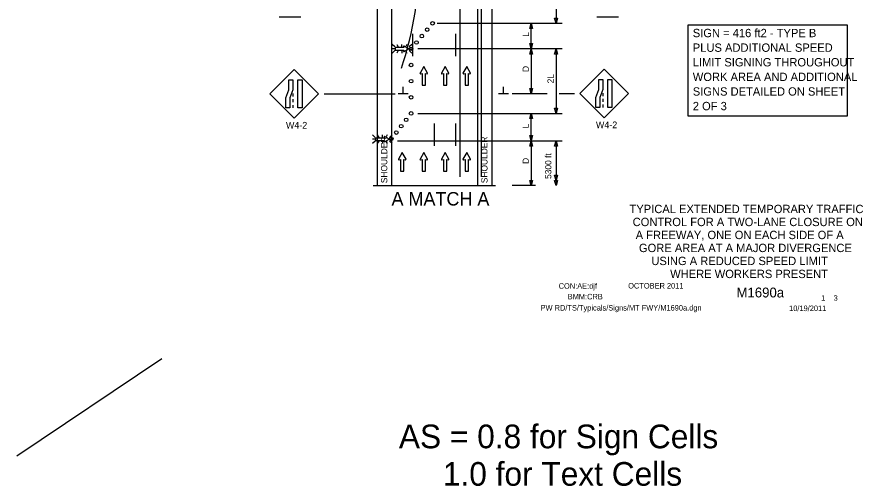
# Model space of a CAD drawing. Extents: x 16486 to 19506, y 5576 to 7023.
# Drawn here: x 16486 to 17431, y 5738 to 6261 of the extents above; entities that cross this region are included whole.
import ezdxf

# ---------------------------------------------------------------- set-up
doc = ezdxf.new("R2010")
doc.units = 0
for name, color, linetype in [('ALI_LEGAL_EX', 7, 'Continuous'), ('BORDER', 7, 'Continuous'), ('BORDER_SIGNAL_WO', 7, 'Continuous'), ('MT_SCRATCH_LEVEL_E', 7, 'Continuous'), ('PAVT_EDGE_EX', 7, 'Continuous'), ('TRAFFIC_SIGNS_PR', 7, 'Continuous'), ('TYPICAL_TEXT_DIMEN_EX', 7, 'Continuous'), ('TYPICAL_TEXT_DIMEN_PR', 7, 'Continuous')]:
    doc.layers.add(name, color=color, linetype=linetype)

msp = doc.modelspace()

# ---------------------------------------------------------------- linework, layer by layer
at = {"layer": 'ALI_LEGAL_EX'}
for p, q in [((16980.24, 6998.86), (16980.24, 6180.72)), ((17004.24, 6998.86), (17004.24, 6180.72)), ((16980.24, 6946.95), (16980.24, 6083.04)), ((17004.24, 6946.95), (17004.24, 6083.04))]:
    msp.add_line(p, q, dxfattribs=at)
for points in [[(16927.96, 6217.56), (16927.96, 6242.56)], [(16975.96, 6217.56), (16975.96, 6242.56)], [(16951.96, 6117.56), (16951.96, 6142.56)], [(16975.96, 6117.56), (16975.96, 6142.56)]]:
    msp.add_lwpolyline(points, dxfattribs=at)
msp.add_arc((16570.62, 6321.73), 364, 341.14744, 21.33821, dxfattribs=at)
at = {"layer": 'MT_SCRATCH_LEVEL_E'}
for p, q in [((16940.06, 6205.93), (16935.95, 6198.69)), ((16944.21, 6198.69), (16940.06, 6205.93)), ((16963.96, 6205.93), (16959.85, 6198.69)), ((16968.11, 6198.69), (16963.96, 6205.93)), ((16988.02, 6205.93), (16983.9, 6198.69)), ((16992.16, 6198.69), (16988.02, 6205.93)), ((16936.43, 6198.01), (16938.21, 6198.32)), ((16938.21, 6198.32), (16938.21, 6185.06)), ((16941.95, 6185.06), (16941.95, 6198.32)), ((16941.95, 6198.32), (16943.73, 6198.01)), ((16960.33, 6198.01), (16962.11, 6198.32)), ((16962.11, 6198.32), (16962.11, 6185.06)), ((16965.85, 6185.06), (16965.85, 6198.32)), ((16965.85, 6198.32), (16967.63, 6198.01)), ((16984.39, 6198.01), (16986.16, 6198.32)), ((16986.16, 6198.32), (16986.16, 6185.06)), ((16989.91, 6185.06), (16989.91, 6198.32)), ((16989.91, 6198.32), (16991.68, 6198.01)), ((16938.21, 6185.06), (16941.95, 6185.06)), ((16962.11, 6185.06), (16965.85, 6185.06)), ((16986.16, 6185.06), (16989.91, 6185.06)), ((16916.15, 6109.95), (16912.04, 6102.71)), ((16912.53, 6102.02), (16914.3, 6102.34)), ((16914.3, 6102.34), (16914.3, 6089.08)), ((16920.3, 6102.71), (16916.15, 6109.95)), ((16918.04, 6089.08), (16918.04, 6102.34)), ((16918.04, 6102.34), (16919.82, 6102.02)), ((16940.06, 6109.95), (16935.95, 6102.71)), ((16936.43, 6102.02), (16938.21, 6102.34)), ((16938.21, 6102.34), (16938.21, 6089.08)), ((16944.21, 6102.71), (16940.06, 6109.95)), ((16941.95, 6089.08), (16941.95, 6102.34)), ((16941.95, 6102.34), (16943.73, 6102.02)), ((16963.96, 6109.95), (16959.85, 6102.71)), ((16960.33, 6102.02), (16962.11, 6102.34)), ((16962.11, 6102.34), (16962.11, 6089.08)), ((16968.11, 6102.71), (16963.96, 6109.95)), ((16965.85, 6089.08), (16965.85, 6102.34)), ((16965.85, 6102.34), (16967.63, 6102.02)), ((16988.02, 6109.95), (16983.9, 6102.71)), ((16984.39, 6102.02), (16986.16, 6102.34)), ((16986.16, 6102.34), (16986.16, 6089.08)), ((16992.16, 6102.71), (16988.02, 6109.95)), ((16989.91, 6089.08), (16989.91, 6102.34)), ((16989.91, 6102.34), (16991.68, 6102.02)), ((16914.3, 6089.08), (16918.04, 6089.08)), ((16938.21, 6089.08), (16941.95, 6089.08)), ((16962.11, 6089.08), (16965.85, 6089.08)), ((16986.16, 6089.08), (16989.91, 6089.08))]:
    msp.add_line(p, q, dxfattribs=at)
for centre, start, end in [((16936.35, 6198.46), 150.42484, 279.96381), ((16943.8, 6198.47), 260.03619, 29.77312), ((16960.26, 6198.46), 150.42484, 279.96381), ((16967.7, 6198.47), 260.03619, 29.77312), ((16984.31, 6198.46), 150.42484, 279.96381), ((16991.75, 6198.47), 260.03619, 29.77312), ((16912.45, 6102.48), 150.42484, 279.96381), ((16919.89, 6102.48), 260.03619, 29.77312), ((16936.35, 6102.48), 150.42484, 279.96381), ((16943.8, 6102.48), 260.03619, 29.77312), ((16960.26, 6102.48), 150.42484, 279.96381), ((16967.7, 6102.48), 260.03619, 29.77312), ((16984.31, 6102.48), 150.42484, 279.96381), ((16991.75, 6102.48), 260.03619, 29.77312)]:
    msp.add_arc(centre, 0.463, start, end, dxfattribs=at)
at = {"layer": 'PAVT_EDGE_EX'}
for p, q in [((16887.96, 6505.27), (16887.96, 6073.13)), ((16903.96, 6505.27), (16903.96, 6073.13)), ((16999.96, 6505.27), (16999.96, 6073.13)), ((17015.96, 6505.27), (17015.96, 6073.13))]:
    msp.add_line(p, q, dxfattribs=at)
at = {"layer": 'TRAFFIC_SIGNS_PR'}
for p, q in [((16778.83, 6261.34), (16802.83, 6261.34)), ((17133.47, 6261.34), (17157.47, 6261.34)), ((16907.74, 6227.8), (16904.92, 6230.62)), ((16907.74, 6225.77), (16904.92, 6225.77)), ((16910.03, 6230.62), (16911.66, 6227.8)), ((16915.82, 6227.8), (16915.82, 6230.62)), ((16921.29, 6230.62), (16920.08, 6228.53)), ((16926.73, 6230.62), (16923.91, 6227.8)), ((16923.91, 6225.77), (16926.73, 6225.77)), ((16907.74, 6223.74), (16904.92, 6220.91)), ((16911.69, 6223.74), (16910.06, 6220.92)), ((16915.82, 6223.74), (16915.82, 6220.92)), ((16920.01, 6223.1), (16921.27, 6220.92)), ((16926.73, 6220.92), (16923.91, 6223.74)), ((16795.32, 6202.52), (16768.17, 6175.37)), ((16822.47, 6175.37), (16795.32, 6202.52)), ((17141.34, 6202.95), (17114.19, 6175.79)), ((17168.49, 6175.79), (17141.34, 6202.95)), ((16768.17, 6175.37), (16795.32, 6148.22)), ((16794.07, 6175.86), (16794.07, 6172.66)), ((16794.07, 6169.46), (16794.07, 6166.26)), ((16795.32, 6148.22), (16822.47, 6175.37)), ((17114.19, 6175.79), (17141.34, 6148.64)), ((17140.09, 6176.29), (17140.09, 6173.09)), ((17140.09, 6169.89), (17140.09, 6166.69)), ((17141.34, 6148.64), (17168.49, 6175.79)), ((16794.07, 6163.06), (16794.07, 6159.86)), ((17140.09, 6163.49), (17140.09, 6160.29)), ((16885.86, 6126.85), (16883.04, 6129.67)), ((16885.86, 6124.82), (16883.04, 6124.82)), ((16885.86, 6122.78), (16883.04, 6119.96)), ((16888.16, 6129.67), (16889.79, 6126.85)), ((16889.81, 6122.78), (16888.19, 6119.96)), ((16893.95, 6126.85), (16893.95, 6129.67)), ((16893.95, 6122.78), (16893.95, 6119.96)), ((16898.13, 6122.15), (16899.39, 6119.96)), ((16899.42, 6129.67), (16898.21, 6127.57)), ((16904.85, 6129.67), (16902.03, 6126.85)), ((16902.03, 6124.82), (16904.85, 6124.82)), ((16904.85, 6119.97), (16902.03, 6122.78))]:
    msp.add_line(p, q, dxfattribs=at)
for points in [[(16917.65, 6228.45), (16917.88, 6227.15), (16908.16, 6227.15), (16908.16, 6224.41), (16917.88, 6224.41), (16917.65, 6223.11)], [(16918.15, 6222.75), (16923.46, 6225.77), (16918.15, 6228.81)], [(16895.78, 6127.5), (16896.01, 6126.2), (16886.28, 6126.2), (16886.28, 6123.46), (16896.01, 6123.46), (16895.77, 6122.15)], [(16896.28, 6121.8), (16901.59, 6124.82), (16896.28, 6127.86)]]:
    msp.add_lwpolyline(points, dxfattribs=at)
for points in [[(16794.07, 6191.11), (16794.07, 6179.93), (16790.73, 6171.04), (16790.73, 6159.86), (16786.24, 6159.86), (16786.24, 6171.04), (16789.58, 6179.93), (16789.58, 6191.11)], [(16804.21, 6191.11), (16804.21, 6159.86), (16799.72, 6159.86), (16799.72, 6191.11)], [(17140.09, 6191.53), (17140.09, 6180.35), (17136.75, 6171.47), (17136.75, 6160.29), (17132.25, 6160.29), (17132.25, 6171.47), (17135.6, 6180.35), (17135.6, 6191.53)], [(17150.23, 6191.53), (17150.23, 6160.29), (17145.73, 6160.29), (17145.73, 6191.53)]]:
    msp.add_lwpolyline(points, close=True, dxfattribs=at)
for centre in [(16949.96, 6254.26), (16949.96, 6254.26), (16943.96, 6247.12), (16931.96, 6232.84), (16937.96, 6239.98), (16925.96, 6225.7), (16925.96, 6207.7), (16925.96, 6189.7), (16925.96, 6171.7), (16925.96, 6153.7), (16914.97, 6139.44), (16920.46, 6146.56), (16909.47, 6132.31), (16903.97, 6125.18)]:
    msp.add_circle(centre, 2, dxfattribs=at)
for centre, start, end in [((16917.98, 6228.51), 61.48329, 189.95933), ((16917.98, 6223.05), 170.73078, 298.89165), ((16896.11, 6127.56), 61.48329, 189.95933), ((16896.11, 6122.1), 170.73078, 298.89165)]:
    msp.add_arc(centre, 0.341, start, end, dxfattribs=at)
at = {"layer": 'TYPICAL_TEXT_DIMEN_EX'}
msp.add_lwpolyline([(17235.24, 6252.57), (17412.74, 6252.57), (17412.74, 6150.46), (17235.24, 6150.46)], close=True, dxfattribs=at)
at = {"layer": 'TYPICAL_TEXT_DIMEN_PR'}
for p, q in [((17087.77, 6335.37), (17087.77, 6254.26)), ((16955.01, 6254.26), (17094.75, 6254.26)), ((17058.39, 6248.4), (17059.96, 6254.26)), ((17059.96, 6225.7), (17059.96, 6254.26)), ((17059.96, 6254.26), (17061.53, 6248.4)), ((17087.77, 6254.26), (17086.2, 6260.12)), ((17086.2, 6260.12), (17087.77, 6260.12)), ((17087.77, 6260.12), (17089.34, 6260.12)), ((17089.34, 6260.12), (17087.77, 6254.26)), ((17059.96, 6248.4), (17058.39, 6248.4)), ((17061.53, 6248.4), (17059.96, 6248.4)), ((17094.75, 6225.7), (16933.47, 6225.7)), ((17059.96, 6225.7), (17058.39, 6231.56)), ((17058.39, 6231.56), (17059.96, 6231.56)), ((17058.39, 6219.83), (17059.96, 6225.7)), ((17059.96, 6231.56), (17061.53, 6231.56)), ((17061.53, 6231.56), (17059.96, 6225.7)), ((17059.96, 6225.7), (17059.96, 6175.7)), ((17059.96, 6225.7), (17061.53, 6219.83)), ((17086.2, 6219.83), (17087.77, 6225.7)), ((17087.77, 6225.7), (17089.34, 6219.83)), ((17087.77, 6225.7), (17087.77, 6153.7)), ((17059.96, 6219.83), (17058.39, 6219.83)), ((17061.53, 6219.83), (17059.96, 6219.83)), ((17087.77, 6219.83), (17086.2, 6219.83)), ((17089.34, 6219.83), (17087.77, 6219.83)), ((16917.25, 6175.7), (16917.25, 6183.48)), ((17029.09, 6175.7), (17029.09, 6183.48)), ((17059.96, 6175.7), (17058.39, 6181.56)), ((17058.39, 6181.56), (17059.96, 6181.56)), ((17059.96, 6181.56), (17061.53, 6181.56)), ((17061.53, 6181.56), (17059.96, 6175.7)), ((16829.06, 6175.7), (16908.26, 6175.7)), ((16922.87, 6175.7), (16911.62, 6175.7)), ((17034.71, 6175.7), (17023.46, 6175.7)), ((17077.74, 6175.7), (17038.96, 6175.7)), ((17108.38, 6175.7), (17091.4, 6175.7)), ((17087.77, 6153.7), (17086.2, 6159.56)), ((17086.2, 6159.56), (17087.77, 6159.56)), ((17087.77, 6159.56), (17089.34, 6159.56)), ((17089.34, 6159.56), (17087.77, 6153.7)), ((16933.47, 6153.7), (17094.75, 6153.7)), ((17058.39, 6147.83), (17059.96, 6153.7)), ((17059.96, 6123.13), (17059.96, 6153.7)), ((17059.96, 6153.7), (17061.53, 6147.83)), ((17059.96, 6147.83), (17058.39, 6147.83)), ((17061.53, 6147.83), (17059.96, 6147.83)), ((16910.92, 6123.13), (17094.75, 6123.13)), ((17059.96, 6123.13), (17058.39, 6128.99)), ((17058.39, 6128.99), (17059.96, 6128.99)), ((17058.39, 6117.27), (17059.96, 6123.13)), ((17059.96, 6128.99), (17061.53, 6128.99)), ((17061.53, 6128.99), (17059.96, 6123.13)), ((17059.96, 6123.13), (17059.96, 6073.13)), ((17059.96, 6123.13), (17061.53, 6117.27)), ((17086.2, 6117.27), (17087.77, 6123.13)), ((17087.77, 6123.13), (17087.77, 6073.13)), ((17087.77, 6123.13), (17089.34, 6117.27)), ((17059.96, 6117.27), (17058.39, 6117.27)), ((17061.53, 6117.27), (17059.96, 6117.27)), ((17087.77, 6117.27), (17086.2, 6117.27)), ((17089.34, 6117.27), (17087.77, 6117.27)), ((17087.77, 6078.91), (17086.2, 6084.77)), ((17086.2, 6084.77), (17087.77, 6084.77)), ((17087.77, 6084.77), (17089.34, 6084.77)), ((17089.34, 6084.77), (17087.77, 6078.91)), ((17059.96, 6073.13), (17058.39, 6078.99)), ((17058.39, 6078.99), (17059.96, 6078.99)), ((17059.96, 6078.99), (17061.53, 6078.99)), ((17061.53, 6078.99), (17059.96, 6073.13)), ((17087.77, 6073.13), (17086.2, 6078.99)), ((17086.2, 6078.99), (17087.77, 6078.99)), ((17087.77, 6078.99), (17089.34, 6078.99)), ((17089.34, 6078.99), (17087.77, 6073.13)), ((16883.66, 6073.13), (17020.31, 6073.13)), ((17064.96, 6073.13), (17038.96, 6073.13)), ((16647.75, 5880), (16485.98, 5771.23))]:
    msp.add_line(p, q, dxfattribs=at)

# ---------------------------------------------------------------- texts
at = {"layer": 'BORDER'}
for s, p in [('TYPICAL EXTENDED TEMPORARY TRAFFIC', (17169.79, 6042.44)), ('CONTROL FOR A TWO-LANE CLOSURE ON', (17173.29, 6027.95)), ('A FREEWAY, ONE ON EACH SIDE OF A', (17176.66, 6013.45)), ('GORE AREA AT A MAJOR DIVERGENCE', (17180.3, 5998.96)), ('USING A REDUCED SPEED LIMIT', (17194.16, 5984.47)), ('WHERE WORKERS PRESENT', (17215.16, 5969.97))]:
    msp.add_text(s, height=9.3, dxfattribs=at).set_placement(p)
at = {"layer": 'BORDER_SIGNAL_WO'}
for s, height, p in [('CON:AE:djf  ', 6.2, (17090.69, 5958.06)), ('    OCTOBER 2011    ', 6.2, (17159.08, 5958.34)), ('BMM:CRB', 6.2, (17100.81, 5946.17)), ('    M1690a   ', 11, (17272.86, 5948.38)), (' 1    3 ', 6.2, (17381.45, 5944.7)), ('PW RD/TS/Typicals/Signs/MT FWY/M1690a.dgn      ', 6.2, (17070.55, 5933.71)), ('10/19/2011    ', 6.2, (17347.93, 5933.13)), ('AS = 0.8 for Sign Cells', 26.4241, (16912.35, 5780.08)), ('     1.0 for Text Cells', 26.4241, (16912.35, 5738.29))]:
    msp.add_text(s, height=height, dxfattribs=at).set_placement(p)
at = {"layer": 'TRAFFIC_SIGNS_PR'}
for p in [(16786.28, 6136.78), (17132.3, 6137.2)]:
    msp.add_text('W4-2', height=7.44, dxfattribs=at).set_placement(p)
at = {"layer": 'TYPICAL_TEXT_DIMEN_EX'}
for s, p in [('SIGN = 416 ft2 - TYPE B', (17240.42, 6238.73)), ('PLUS ADDITIONAL SPEED', (17240.42, 6222.43)), ('LIMIT SIGNING THROUGHOUT', (17240.42, 6206.13)), ('WORK AREA AND ADDITIONAL', (17240.42, 6189.83)), ('SIGNS DETAILED ON SHEET', (17240.42, 6173.53)), ('2 OF 3', (17240.42, 6157.23))]:
    msp.add_text(s, height=9.3, dxfattribs=at).set_placement(p)
at = {"layer": 'TYPICAL_TEXT_DIMEN_PR'}
for s, p in [('L', (17057.49, 6239.34)), ('D', (17057.4, 6199.92)), ('2L', (17085.21, 6187.2)), ('L', (17057.4, 6136.99)), ('SHOULDER', (16899.4, 6075.84)), ('SHOULDER', (17011.26, 6075.84)), ('D', (17057.4, 6097.35)), ('5300 ft', (17082.57, 6080.58))]:
    msp.add_text(s, height=7, rotation=90, dxfattribs=at).set_placement(p)
msp.add_text('A MATCH A', height=15, dxfattribs=at).set_placement((16904.13, 6050.94))

doc.saveas('drawing.dxf')
